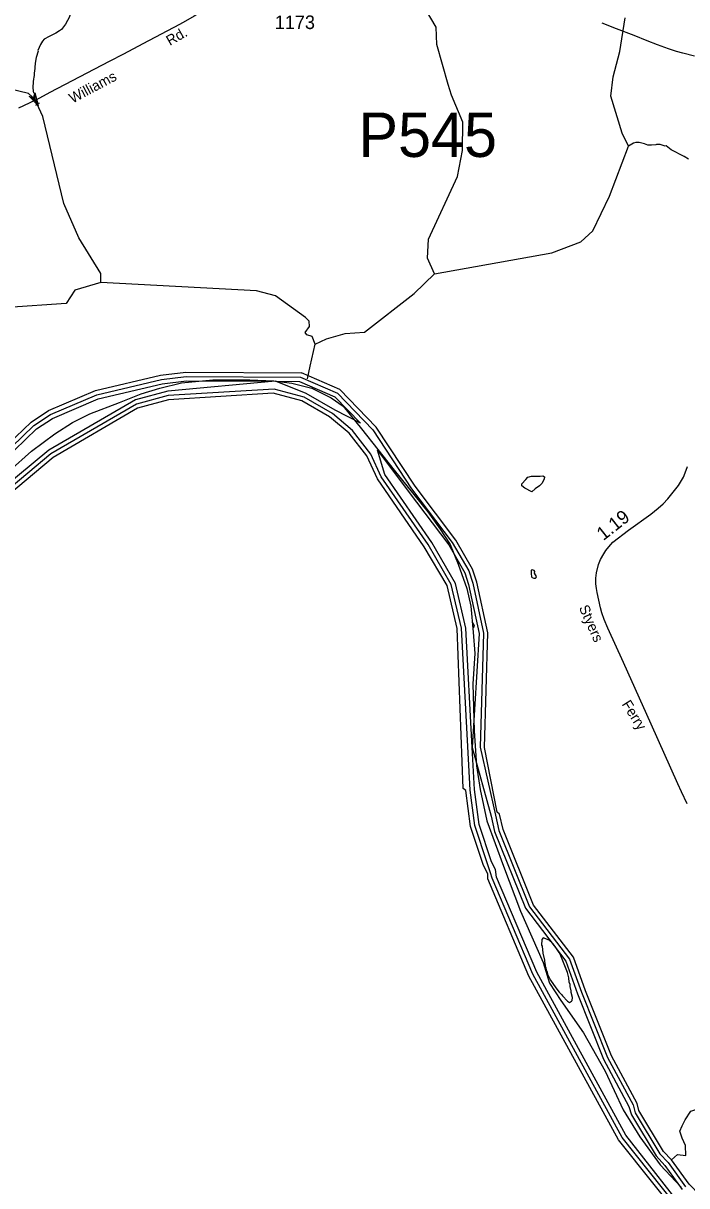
# Model space of a CAD drawing. Extents: x 1547597 to 1699558, y 810033 to 920809.
# Drawn here: x 1564751 to 1570886, y 837485 to 848225 of the extents above; entities that cross this region are included whole.
import ezdxf

# ---------------------------------------------------------------- set-up
doc = ezdxf.new("R2010")
doc.units = 0
for name, color, linetype in [('Exist Boundary Political CountyLine', 7, 'Continuous'), ('Exist Hydrographic Bay Label', 7, 'Continuous'), ('Exist Hydrographic Buffer Line', 7, 'Continuous'), ('Exist Hydrographic Creek Single Shore', 7, 'Continuous'), ('Exist Hydrographic Misc Water Feature', 7, 'Continuous'), ('Exist Road Secondary Mileage Hundredths English Label', 7, 'Continuous'), ('Exist Road Secondary Structure Pipe Attributed CELL', 7, 'Continuous'), ('Exist Road Secondary Structure Pipe CELL', 7, 'Continuous'), ('Exist Road Secondary Structure Pipe Number Label', 7, 'Continuous'), ('Exist Road Secondary Type 51 Attributed', 7, 'Continuous'), ('Exist Road Secondary Type 51 Label', 7, 'Continuous'), ('Exist Road Secondary Type 51 Number Label', 7, 'Continuous')]:
    doc.layers.add(name, color=color, linetype=linetype)

msp = doc.modelspace()

# ---------------------------------------------------------------- linework, layer by layer
at = {"layer": 'Exist Boundary Political CountyLine'}
msp.add_lwpolyline([(1564622, 844086), (1564827, 844272), (1565044, 844431), (1565207, 844537), (1565366, 844616), (1565640, 844722), (1565841, 844802), (1566013, 844855), (1566216, 844903), (1566503, 844930), (1566847, 844930), (1567068, 844921), (1567236, 844899), (1567421, 844855), (1567598, 844766), (1567708, 844687), (1567880, 844479), (1568180, 844095), (1568492, 843711), (1568606, 843552), (1568699, 843410), (1568774, 843229), (1568854, 843004), (1568891, 842841), (1568913, 842598), (1568926, 842403), (1568909, 842121), (1568920, 841688), (1568942, 841365), (1568977, 841145), (1569039, 840857), (1569191, 840438), (1569350, 840023), (1569560, 839546), (1569617, 839356), (1569723, 839197), (1569931, 838896), (1570132, 838543), (1570299, 838185), (1570454, 837938), (1570639, 837677), (1570836, 837470)], dxfattribs=at)
at = {"layer": 'Exist Hydrographic Bay Label'}
for points in [[(1563811, 842536), (1563824, 842844), (1563895, 843135), (1564238, 843840), (1564612, 844335), (1564824, 844541), (1564984, 844646), (1565420, 844831), (1566022, 844973), (1566256, 845001), (1567323, 844996)], [(1570744, 837724), (1570670, 837801), (1570442, 838180), (1570427, 838246), (1570191, 838684), (1569950, 839286), (1569838, 839597), (1569470, 840078), (1569188, 840776), (1569156, 840918), (1569132, 840935), (1569015, 841534), (1569047, 842594), (1568946, 843062), (1568906, 843181), (1568751, 843450), (1568375, 843947), (1568016, 844493), (1567679, 844841), (1567323, 844996)], [(1570877, 837131), (1570255, 837908), (1569427, 839422), (1569048, 840319), (1569048, 840368), (1569008, 840445), (1568888, 840805), (1568843, 841137), (1568818, 841154), (1568764, 842633), (1568670, 843032), (1568459, 843387), (1568026, 844017), (1567929, 844229), (1567765, 844439), (1567584, 844590), (1567328, 844736), (1567062, 844808), (1566094, 844745), (1565809, 844669), (1565027, 844212), (1564605, 843859)], [(1576500, 831023), (1576344, 831134), (1575284, 832216), (1574978, 832419), (1574168, 832849), (1573820, 833112), (1573486, 833516), (1573216, 833981), (1573153, 834163), (1573096, 834233), (1572740, 835061), (1572606, 835523), (1572581, 835540), (1572581, 835589), (1572371, 836050), (1572346, 836060), (1572330, 836120), (1572159, 836330), (1571822, 836659), (1571434, 836959), (1570909, 837498), (1570744, 837724)]]:
    msp.add_lwpolyline(points, dxfattribs=at)
at = {"layer": 'Exist Hydrographic Buffer Line'}
for points in [[(1567083, 844917), (1566089, 844825), (1565789, 844746), (1564987, 844281), (1564554, 843921), (1564383, 843721), (1564167, 843299), (1564022, 842805), (1563962, 842323), (1563892, 842542), (1563904, 842833), (1563971, 843108), (1564307, 843798), (1564672, 844282), (1564875, 844478), (1565022, 844575), (1565445, 844755), (1566036, 844894), (1566261, 844921), (1567083, 844917)], [(1564642, 844309), (1564850, 844510), (1565003, 844611), (1565433, 844793), (1566029, 844934), (1566259, 844961), (1567315, 844956), (1567656, 844807), (1567985, 844468), (1568342, 843925), (1568718, 843428), (1568870, 843165), (1568908, 843052), (1569007, 842590), (1568975, 841536), (1569117, 840909), (1569149, 840767), (1569433, 840063), (1569803, 839578), (1569913, 839273), (1570154, 838669), (1570390, 838232), (1570408, 838159), (1570636, 837781), (1570714, 837699), (1570876, 837474)], [(1567083, 844917), (1567307, 844916), (1567633, 844774), (1567870, 844529), (1567636, 844651), (1567368, 844806), (1567083, 844917)], [(1570915, 837144), (1570289, 837930), (1569464, 839439), (1569088, 840327), (1569073, 840376), (1569045, 840460), (1568928, 840814), (1568883, 841141), (1568804, 842635), (1568709, 843041), (1568494, 843408), (1568061, 844036), (1567966, 844245), (1567797, 844463), (1567610, 844621), (1567348, 844771), (1567073, 844846), (1566092, 844785), (1565799, 844707), (1565007, 844246), (1564580, 843890)], [(1568903, 841535), (1568844, 842637), (1568748, 843050), (1568528, 843428), (1568096, 844056), (1568028, 844281), (1568309, 843903), (1568685, 843406), (1568833, 843148), (1568869, 843041), (1568967, 842587), (1568903, 841535)], [(1568903, 841535), (1569078, 840900), (1569110, 840758), (1569396, 840048), (1569767, 839559), (1569875, 839259), (1570117, 838654), (1570352, 838218), (1570374, 838139), (1570602, 837760), (1570683, 837673), (1570844, 837451)], [(1570956, 837146), (1570322, 837953), (1569500, 839457), (1569128, 840335), (1569119, 840406), (1569082, 840476), (1568967, 840823), (1568923, 841145), (1568903, 841535)]]:
    msp.add_lwpolyline(points, dxfattribs=at)
at = {"layer": 'Exist Hydrographic Creek Single Shore'}
for points in [[(1568553, 845910), (1568489, 846056), (1568500, 846229), (1568767, 846808), (1568812, 847050), (1568815, 847310), (1568711, 847561), (1568679, 847660), (1568576, 848030), (1568570, 848188), (1568439, 848407)], [(1568553, 845910), (1569640, 846105), (1569908, 846207), (1570018, 846307), (1570173, 846629), (1570347, 847090), (1570290, 847211), (1570183, 847551), (1570206, 847731), (1570267, 847963), (1570317, 848274)], [(1565468, 845831), (1565469, 845913), (1565265, 846242), (1565128, 846560), (1564931, 847365), (1564859, 847524), (1564801, 847575), (1564477, 847653)], [(1567452, 845259), (1567556, 845309), (1567728, 845359), (1567908, 845371), (1568367, 845730), (1568553, 845910)], [(1567452, 845259), (1567422, 845332), (1567373, 845347), (1567357, 845367), (1567399, 845424), (1567395, 845474), (1567360, 845507), (1567083, 845707), (1566909, 845753), (1565468, 845831)], [(1567380, 844939), (1567403, 845057), (1567452, 845259)], [(1570744, 837724), (1570801, 837773), (1570878, 837763), (1570875, 837858), (1570844, 837923), (1570821, 837988), (1570844, 838038), (1570871, 838095), (1570924, 838175), (1571012, 838206), (1571008, 838298), (1570997, 838374), (1571043, 838439), (1571140, 838511), (1571267, 838728), (1571328, 838901), (1571430, 839040), (1571506, 839091), (1571574, 839080), (1571771, 838977), (1571980, 838966)]]:
    msp.add_lwpolyline(points, dxfattribs=at)
at = {"layer": 'Exist Hydrographic Misc Water Feature'}
for points in [[(1565219, 848424), (1565212, 848389), (1565204, 848360), (1565189, 848317), (1565176, 848279), (1565162, 848251), (1565142, 848218), (1565123, 848193), (1565104, 848169), (1565086, 848154), (1565053, 848134), (1565022, 848119), (1564990, 848102), (1564945, 848078), (1564930, 848060), (1564911, 848029)], [(1564911, 848029), (1564887, 847973), (1564888, 847969), (1564870, 847909), (1564861, 847857), (1564856, 847777), (1564852, 847769), (1564852, 847737), (1564848, 847729), (1564847, 847705), (1564843, 847690), (1564841, 847626), (1564846, 847580)], [(1570901, 846970), (1570862, 846994), (1570743, 847056), (1570695, 847092), (1570688, 847090), (1570639, 847105), (1570607, 847105), (1570599, 847101), (1570559, 847098), (1570527, 847098), (1570495, 847111), (1570447, 847123), (1570415, 847124), (1570393, 847118), (1570347, 847090)], [(1565468, 845831), (1565227, 845758), (1565149, 845635), (1564610, 845600), (1564344, 845846), (1564210, 845926), (1563690, 846010), (1563609, 845999), (1563314, 846219), (1563139, 846223), (1562226, 845953), (1561718, 845960), (1561353, 846082)], [(1569397, 844010), (1569417, 844030), (1569451, 844041), (1569531, 844040), (1569555, 844044), (1569571, 844036), (1569567, 844014), (1569546, 843972), (1569526, 843950), (1569486, 843925), (1569453, 843897), (1569390, 843930), (1569360, 843952), (1569362, 843970), (1569397, 844010)], [(1569447, 843141), (1569452, 843110), (1569458, 843104), (1569472, 843097), (1569488, 843097), (1569494, 843103), (1569496, 843113), (1569480, 843145), (1569481, 843161), (1569477, 843169), (1569457, 843175), (1569449, 843172), (1569447, 843141)], [(1568909, 842641), (1568919, 842646), (1568923, 842656), (1568919, 842670), (1568909, 842685), (1568905, 842686)], [(1569584, 839497), (1569585, 839481), (1569597, 839457), (1569600, 839441), (1569628, 839385), (1569677, 839312), (1569708, 839272), (1569732, 839248), (1569736, 839240), (1569784, 839191), (1569801, 839179), (1569821, 839189), (1569827, 839195), (1569830, 839223), (1569818, 839271), (1569819, 839287), (1569807, 839327), (1569807, 839343), (1569800, 839367), (1569796, 839407), (1569785, 839455), (1569722, 839608), (1569707, 839640), (1569669, 839696), (1569648, 839723), (1569614, 839753), (1569560, 839774), (1569546, 839760), (1569544, 839706), (1569548, 839698), (1569555, 839634), (1569570, 839570), (1569570, 839554), (1569574, 839546), (1569577, 839514), (1569584, 839497)]]:
    msp.add_lwpolyline(points, dxfattribs=at)
at = {"layer": 'Exist Road Secondary Structure Pipe Attributed CELL'}
msp.add_lwpolyline([(1564860, 847583), (1564889, 847464), (1564805, 847552), (1564860, 847518)], close=True, dxfattribs=at)
at = {"layer": 'Exist Road Secondary Structure Pipe CELL'}
for p, q in [((1564851, 847566), (1564845, 847541)), ((1564820, 847546), (1564845, 847541)), ((1564845, 847541), (1564877, 847490)), ((1564871, 847465), (1564877, 847490)), ((1564902, 847485), (1564877, 847490))]:
    msp.add_line(p, q, dxfattribs=at)
at = {"layer": 'Exist Road Secondary Type 51 Attributed'}
for points in [[(1566663, 848510), (1566518, 848412), (1566443, 848362), (1566399, 848333), (1566332, 848291), (1566253, 848246), (1566196, 848214), (1565857, 848035), (1565677, 847941), (1565546, 847872), (1564997, 847587), (1564901, 847534), (1564807, 847487), (1564706, 847441)], [(1570959, 847922), (1570849, 847949), (1570792, 847964), (1570717, 847988), (1570615, 848026), (1570521, 848063), (1570399, 848113), (1570238, 848175), (1570103, 848227)], [(1570889, 841012), (1570838, 841124), (1570804, 841198), (1570558, 841749), (1570302, 842319), (1570158, 842636), (1570124, 842717), (1570102, 842778), (1570088, 842825), (1570057, 842967), (1570051, 843002), (1570046, 843047), (1570045, 843098), (1570051, 843149), (1570071, 843226), (1570089, 843270), (1570120, 843324), (1570138, 843355), (1570165, 843389), (1570204, 843430), (1570347, 843543), (1570555, 843690), (1570623, 843744), (1570667, 843786), (1570712, 843830), (1570773, 843907), (1570809, 843956), (1570855, 844033), (1570873, 844071), (1570893, 844129)]]:
    msp.add_lwpolyline(points, dxfattribs=at)

# ---------------------------------------------------------------- texts
at = {"layer": 'Exist Road Secondary Mileage Hundredths English Label'}
msp.add_text('1.19', height=125, rotation=38.2272, dxfattribs=at).set_placement((1570115, 843440))
at = {"layer": 'Exist Road Secondary Structure Pipe Number Label'}
msp.add_text('P545', height=410.1, dxfattribs=at).set_placement((1567851, 846990))
at = {"layer": 'Exist Road Secondary Type 51 Label'}
for s, rotation, p in [('Rd.', 29.7549, (1566107, 848015)), ('Williams', 27.9447, (1565207, 847483)), ('Styers', 294.0431, (1569887, 842826)), ('Ferry', 302.2782, (1570282, 841934))]:
    msp.add_text(s, height=95, rotation=rotation, dxfattribs=at).set_placement(p)
at = {"layer": 'Exist Road Secondary Type 51 Number Label'}
msp.add_text('1173', height=125, dxfattribs=at).set_placement((1567077, 848172))

doc.saveas('drawing.dxf')
